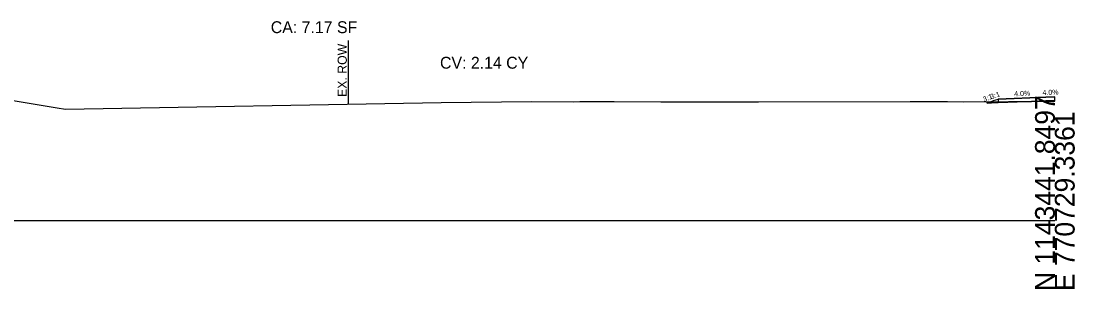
# Model space of a CAD drawing. Extents: x -26 to 5403, y -13 to 9553.
# Drawn here: x 4253.7 to 4402.8, y 1990.3 to 2028.2 of the extents above; entities that cross this region are included whole.
import ezdxf

# ---------------------------------------------------------------- set-up
doc = ezdxf.new("R2010")
doc.units = 0
for name, color, linetype in [('CONST_LV3', 7, 'Continuous'), ('DTM_P_FINISHED_GRADE', 7, 'Continuous'), ('DTM_X_GROUND', 7, 'Continuous'), ('SLOPE_STAKES_FILL', 7, 'Continuous'), ('X_ROW', 7, 'Continuous'), ('XS_CELL', 7, 'Continuous'), ('XS_M_SHAPES_EARTHWORK', 7, 'Continuous'), ('XS_P_DR_GRAVEL', 7, 'Continuous'), ('XS_P_GROUND', 7, 'Continuous'), ('XS_P_TX_FS_BS', 7, 'Continuous'), ('XS_SHEET_EW_TX_AREA', 7, 'Continuous'), ('XS_SHEET_EW_TX_VOLUME', 7, 'Continuous')]:
    doc.layers.add(name, color=color, linetype=linetype)

msp = doc.modelspace()

# ---------------------------------------------------------------- linework, layer by layer
at = {"layer": 'CONST_LV3'}
msp.add_lwpolyline([(4392, 2017.15), (4396.08, 2017.31), (4400, 2017.47)], dxfattribs=at)
at = {"layer": 'DTM_P_FINISHED_GRADE'}
msp.add_lwpolyline([(4392, 2017.15), (4398.74, 2017.42), (4400, 2017.47)], dxfattribs=at)
at = {"layer": 'DTM_X_GROUND'}
msp.add_lwpolyline([(4252.29, 2017), (4258.8, 2015.91), (4259.99, 2015.72), (4313.13, 2016.69), (4325.92, 2016.81), (4331.89, 2016.77), (4332.78, 2016.79), (4337.63, 2016.79), (4344.25, 2016.78), (4358.07, 2016.76), (4379.54, 2016.79), (4384.8, 2016.8), (4387.05, 2016.76), (4393.44, 2016.8), (4400, 2016.87)], dxfattribs=at)
at = {"layer": 'X_ROW'}
msp.add_line((4300, 2025.45), (4300, 2016.45), dxfattribs=at)
at = {"layer": 'XS_CELL'}
msp.add_line((4200, 2000), (4400, 2000), dxfattribs=at)
at = {"layer": 'XS_M_SHAPES_EARTHWORK'}
for points in [[(4390.4, 2016.58), (4390.4, 2016.78), (4393.44, 2016.8), (4396.7, 2016.83), (4392, 2016.65), (4391.04, 2016.61)], [(4396.7, 2016.83), (4400, 2016.87), (4400, 2016.97), (4398.74, 2016.92)]]:
    msp.add_lwpolyline(points, close=True, dxfattribs=at)
at = {"layer": 'XS_P_DR_GRAVEL'}
for points in [[(4390.4, 2016.58), (4391.04, 2016.61), (4392, 2016.65)], [(4400, 2016.97), (4400, 2017.47), (4400, 2017.47), (4398.74, 2017.42), (4398.74, 2017.42), (4392, 2017.15), (4392, 2017.15), (4392, 2016.65), (4392, 2016.65), (4398.74, 2016.92), (4398.74, 2016.92), (4400, 2016.97)]]:
    msp.add_lwpolyline(points, dxfattribs=at)
at = {"layer": 'XS_P_GROUND'}
msp.add_lwpolyline([(4390.9, 2016.78), (4391.34, 2016.93), (4392, 2017.15)], dxfattribs=at)

# ---------------------------------------------------------------- texts
at = {"layer": 'SLOPE_STAKES_FILL'}
msp.add_text('X', height=0.012, dxfattribs=at).set_placement((4390.9, 2016.78))
at = {"layer": 'X_ROW'}
msp.add_text('EX. ROW', height=1.3, rotation=90, dxfattribs=at).set_placement((4299.8, 2017.45))
at = {"layer": 'XS_CELL'}
for s, p in [('N 1143441.8497', (4400, 1990)), ('E 770729.3361', (4402.8, 1990))]:
    msp.add_text(s, height=2.8, rotation=90, dxfattribs=at).set_placement(p)
at = {"layer": 'XS_P_TX_FS_BS'}
for s, rotation, p in [('3:1', 21.5127, (4389.97, 2016.74)), ('3:1', 18.4349, (4391, 2017.13)), ('4.0%', 2.2909, (4394.26, 2017.54)), ('4.0%', 2.2904, (4398.26, 2017.7))]:
    msp.add_text(s, height=0.72, rotation=rotation, dxfattribs=at).set_placement(p)
at = {"layer": 'XS_SHEET_EW_TX_AREA'}
msp.add_text('CA: 7.17 SF', height=1.68, dxfattribs=at).set_placement((4289.04, 2026.48))
at = {"layer": 'XS_SHEET_EW_TX_VOLUME'}
msp.add_text('CV: 2.14 CY', height=1.68, dxfattribs=at).set_placement((4312.99, 2021.45))

doc.saveas('drawing.dxf')
